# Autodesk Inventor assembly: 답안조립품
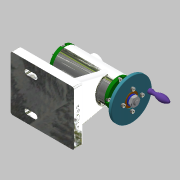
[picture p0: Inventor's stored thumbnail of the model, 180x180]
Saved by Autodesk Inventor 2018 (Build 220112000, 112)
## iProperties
Created: 2022-06
Part Number: 답안조립품
Material: 일반
Document SubType Name: Assembly
Designer: home
Author: home
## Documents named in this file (18)
- C:\Users\home\Desktop\720606V1018\답안조립품.iam
- C:\Users\home\Desktop\720606V1018\본체.ipt
- C:\Users\home\Desktop\720606V1018\슬리브.ipt
- C:\Users\home\Desktop\720606V1018\나사.ipt
- C:\Users\home\Desktop\720606V1018\중공축.ipt
- C:\Users\home\Desktop\720606V1018\센터홀더.ipt
- C:\Users\home\Desktop\720606V1018\센터.ipt
- C:\Users\home\Desktop\720606V1018\볼트 M3.ipt
- C:\Users\home\Desktop\720606V1018\커버.ipt
- C:\Users\home\Desktop\720606V1018\부시.ipt
- C:\Users\home\Desktop\720606V1018\나사축.ipt
- C:\Users\home\Desktop\720606V1018\키 4 x 4 x 10.ipt
- C:\Users\home\Desktop\720606V1018\플랜지.ipt
- C:\Users\home\Desktop\720606V1018\돌림판.ipt
- C:\Users\home\Desktop\720606V1018\핸들.ipt
- C:\Users\home\Desktop\720606V1018\와셔.ipt
- C:\Users\home\Desktop\720606V1018\너트 M8.ipt
- C:\Users\home\Desktop\720606V1018\멈춤나사 M3.ipt
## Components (2 placed, 2 different names)
1. 플랜지:1
2. 핸들:1
